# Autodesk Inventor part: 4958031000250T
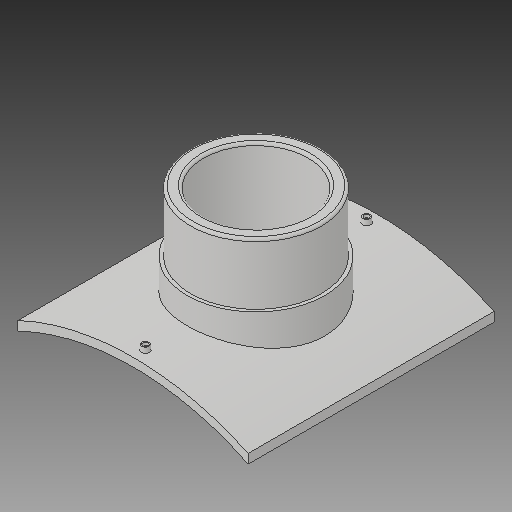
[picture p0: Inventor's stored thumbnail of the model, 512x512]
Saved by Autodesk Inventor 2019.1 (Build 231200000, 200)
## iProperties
Created: 2017-10
Part Number: 4958031000250T
Material: Generic
Description: PLASSON BRANCH SADDLE 1000x250
Document SubType Name: Modeling
Designer: KIM
Mass: 2754.05 g
Surface Area: 3037.44 cm^2
Volume: 2754.05 cm^3
Density: 1 g/cm^3
Appearance: Default
Author: KIM
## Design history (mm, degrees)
derived "495803.ipt"
feature "Solid1::495803.ipt"
tag "TaggingFeature1"
body "Solid1"
other parameters: "d1" = 16, "d4" = 0, "d12" = 525.6, "d13" = 14, "d14" = 211.5, "d16" = 5 deg, "d18" = 4, "d19" = 14, "d20" = 0, "d21" = 3, "d22" = 0, "d23" = 683, "d24" = 262.5, "d25" = 16, "d28" = 0, "d29" = 9.6, "d31" = 0, "d32" = 83.5, "d33" = 0, "d37" = 116.9, "d38" = 0, "d39" = 5, "H_" = 167, "x_" = 16, "D_" = 16
